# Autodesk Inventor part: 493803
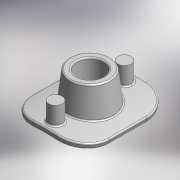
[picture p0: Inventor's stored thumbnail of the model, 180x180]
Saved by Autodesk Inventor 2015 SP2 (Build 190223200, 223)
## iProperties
Created: 2019-01
Part Number: 493803
Material: PVC-Piping
Description: PLASSON SENSOR ADAPTOR 1''
Document SubType Name: Modeling
Designer: KIM
Mass: 126.979 g
Surface Area: 263.015 cm^2
Volume: 90.6994 cm^3
Density: 1.4 g/cm^3
Appearance: Smooth - White
Author: KIM
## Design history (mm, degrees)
derived "493803.ipt"
feature "Solid1::493803.ipt" dims "ScaleForDerivedMember" = 10
tag "TaggingFeature1"
body "Solid1"
other parameters: "d0" = 38 [user parameter], "d1" = 103 [user parameter], "d4" = 85 [user parameter], "d6" = 206 [user parameter], "d8" = 103 [user parameter], "d9" = 0 [user parameter], "d10" = 26.6 [user parameter], "d11" = 26.6 [user parameter], "d13" = 12.36 [user parameter], "d14" = 12.36 [user parameter], "d15" = 30.291 [user parameter], "d16" = 54.5238 [user parameter], "d17" = 45.4365 [user parameter], "d18" = 15.1455 [user parameter], "d20" = 15.1455 [user parameter], "d24" = 30.291 [user parameter], "d25" = 1.51455 [user parameter], "d27" = 0 [user parameter], "Rp" = 30.291 [user parameter], "H_" = 38 [user parameter], "B" = 85 [user parameter], "L" = 103 [user parameter]
